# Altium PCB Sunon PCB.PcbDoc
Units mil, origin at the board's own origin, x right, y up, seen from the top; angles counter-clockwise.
Board outline 865.99 x 865.99 mil, 2 copper layers (Top Layer, Bottom Layer), stack 64.8 mil thick; 18 components, 17 nets, 70 pads, 87 vias.
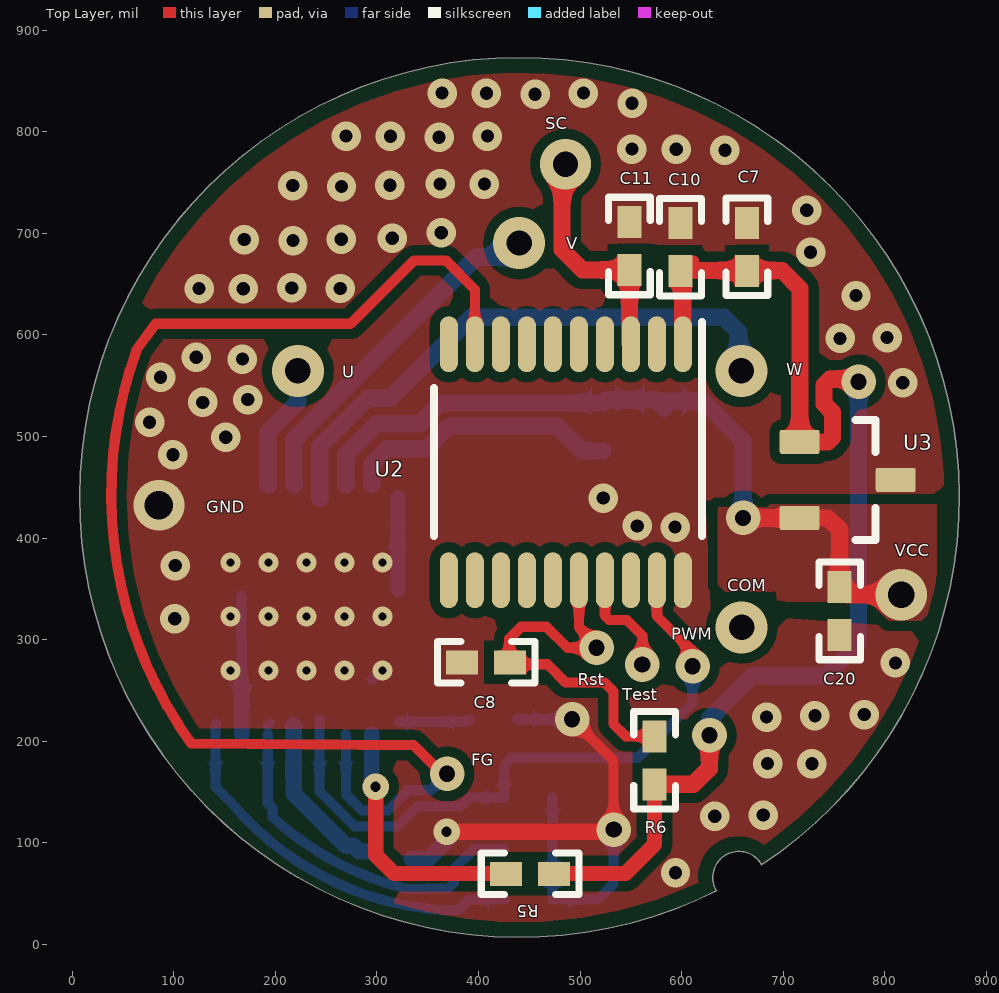
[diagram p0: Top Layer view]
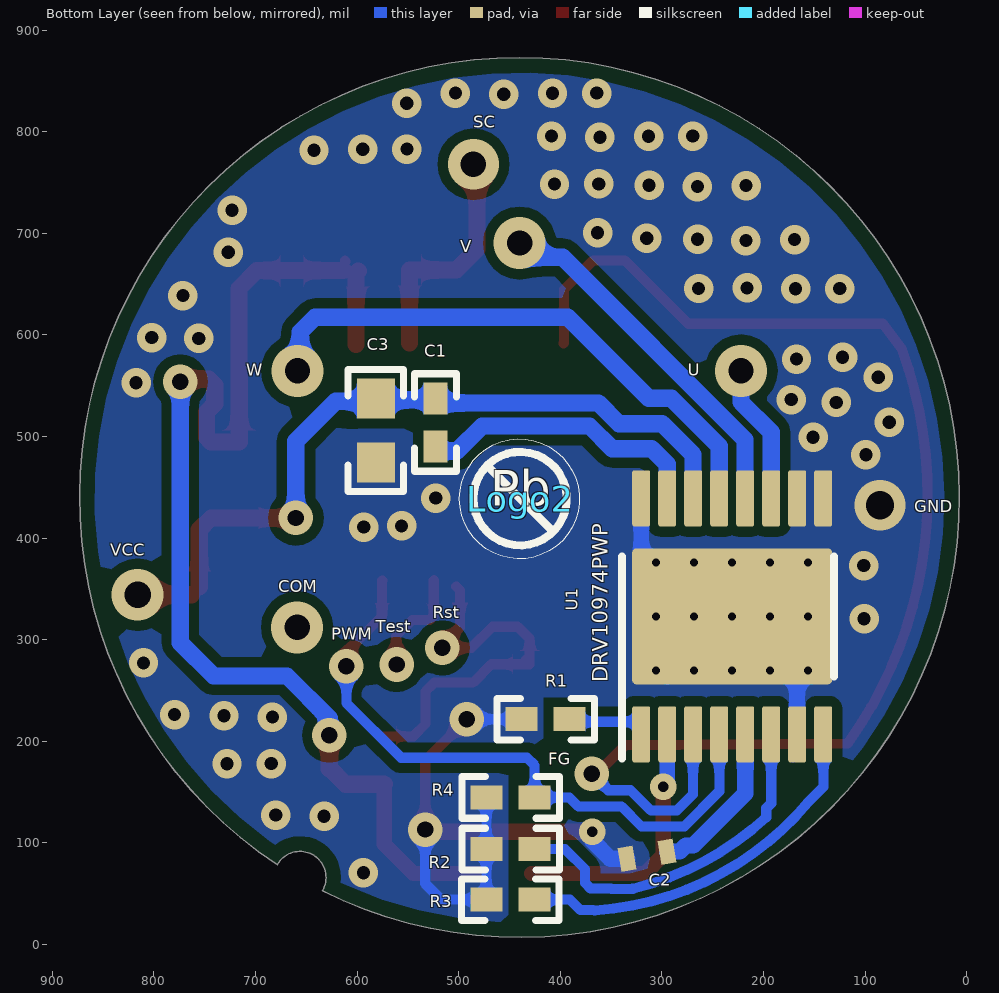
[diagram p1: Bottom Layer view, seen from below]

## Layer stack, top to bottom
Top Solder: solder mask 0.4, Solder Resist, Dk 3.5
Top Layer: signal copper 2.8
Dielectric1: core 59.2, FR-4, Dk 4.8
Bottom Layer: signal copper 2.8
Bottom Solder: solder mask 0.4, Solder Resist, Dk 3.5

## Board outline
634.23,52.84 cw(c440.24,439.95) 678.49,78.39 678.38,78.8 ccw(c656.2,66)

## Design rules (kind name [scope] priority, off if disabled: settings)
AcuteAngle [All] p1: minimum=4.50000000000000E+0001 checktracksonly=FALSE
AssemblyTestPointUsage [All] p1: valid=2
BoardOutlineClearance BoardOutlineClearance_MountingHoles [OnCopper and InComponentClass('Mounting Holes')] p1: gap=15 ignorepadtopadclearanceinfootprint=FALSE
BoardOutlineClearance BoardOutlineClearance_Poly [OnCopper and IsPoly] p2: gap=15 ignorepadtopadclearanceinfootprint=FALSE
BoardOutlineClearance [OnCopper and Not InComponentClass('Logo') and not InComponentClass('FiducialMark') and not InRegion(1000,500,4000,800) and not InPoly] p3: gap=1 ignorepadtopadclearanceinfootprint=FALSE
Clearance Clearance_Keepouts [((IsTrack Or IsArc) And Not InPoly) And IsFree and IsKeepOut vs ((IsTrack Or IsArc) And Not InPoly) And IsFree and IsKeepOut] p1: gap=2 ignorepadtopadclearanceinfootprint=FALSE
Clearance Clearance_Poly [InPolygon] p2: gap=10 ignorepadtopadclearanceinfootprint=FALSE
Clearance Clearance_FiducialMark [IsKeepOut and InComponentClass('FiducialMark') vs IsPad and InComponentClass('FiducialMark')] p3: gap=0 ignorepadtopadclearanceinfootprint=FALSE
Clearance [All] p4: gap=5 ignorepadtopadclearanceinfootprint=FALSE
ComponentClearance ComponentClearance_MountingHoles_FiducialMarks [InComponentClass('Mounting Holes') vs InComponentClass('FiducialMark')] p1: gap=50 collisioncheckmode=3 verticalgap=10 showdistances=FALSE
ComponentClearance ComponentClearance_Shunt [InComponentClass('Header') vs InComponentClass('Shunt')] p2: gap=0 collisioncheckmode=3 verticalgap=0 showdistances=FALSE
ComponentClearance ComponentClearance_Logo [InComponentClass('Logo')] p3: gap=50 collisioncheckmode=3 verticalgap=10 showdistances=FALSE
ComponentClearance ComponentClearance_ScrewToNut [(HasFootprint('NY PMS 440 0025 PH')) vs (HasFootprint('Keystone_1902C'))] p4: gap=5 collisioncheckmode=3 verticalgap=10 showdistances=FALSE
ComponentClearance ComponentClearance_MountingHoles [InComponentClass('Mounting Holes')] p5: gap=250 collisioncheckmode=3 verticalgap=100000 showdistances=FALSE
ComponentClearance ComponentClearance_SmallPassives [HasFootprint('0201*') or HasFootprint('0402*') or HasFootprint('0508') or HasFootprint('0603*') or HasFootprint('0612') or HasFootprint('0805*') or HasFootprint('0815*') or HasFootprint('0830*') or HasFootprint('1206*') or HasFootprint('1210*') or HasFootprint('1808*') or HasFootprint('1812*') or HasFootprint('1825*') or HasFootprint('2010*') or HasFootprint('2220*') or HasFootprint('2225*') or HasFootprint('2512*') or HasFootprint('2728*') or HasFootprint('3518*') vs HasFootprint('0201*') or HasFootprint('0402*') or HasFootprint('0508') or HasFootprint('0603*') or HasFootprint('0612') or HasFootprint('0805*') or HasFootprint('0815*') or HasFootprint('0830*') or HasFootprint('1206*') or HasFootprint('1210*') or HasFootprint('1808*') or HasFootprint('1812*') or HasFootprint('1825*') or HasFootprint('2010*') or HasFootprint('2220*') or HasFootprint('2225*') or HasFootprint('2512*') or HasFootprint('2728*') or HasFootprint('3518*')] p6: gap=14.96 collisioncheckmode=3 verticalgap=10 showdistances=FALSE
ComponentClearance ComponentClearance_THtoSMT [IsThruComponent vs IsSMTComponent] p7: gap=40 collisioncheckmode=3 verticalgap=30 showdistances=FALSE
ComponentClearance ComponentClearance_THtoTH [IsThruComponent vs IsThruComponent] p8: gap=30 collisioncheckmode=3 verticalgap=30 showdistances=FALSE
ComponentClearance [All] p9: gap=5 collisioncheckmode=3 verticalgap=5 showdistances=FALSE
DiffPairsRouting [All] p1: maxlimit=100 minlimit=10 mostfreqgap=10 toplayer_minwidth=15 toplayer_maxwidth=15 toplayer_prefwidth=15 bottomlayer_minwidth=15 bottomlayer_maxwidth=15 bottomlayer_prefwidth=15 maxuncoupledlength=1000
FabricationTestPointUsage TestPointUsage [All] p1: valid=2 allowmultiple=FALSE
FabricationTestpoint Testpoint [All] p1: side=3 testpointundercomponent=TRUE minsize=40 maxsize=100 preferedsize=60 minholesize=0 maxholesize=40 preferedholesize=32 testpointgrid=1 allowsidetop=TRUE allowsidebottom=TRUE usegrid=TRUE gridtolerance=0.01
FanoutControl Fanout_LCC [IsLCC] p1: bgadir=Out bgaviamode=Centered fanoutstyle=Auto fanoutdirection=Alternating viagrid=1 // Fanout_LCC (Default Rule)
FanoutControl Fanout_BGA [IsBGA] p2: bgadir=Out bgaviamode=Centered fanoutstyle=Auto fanoutdirection=Alternating viagrid=1 // Fanout_BGA (Default Rule)
FanoutControl Fanout_Default [All] p4: bgadir=Out bgaviamode=Centered fanoutstyle=Auto fanoutdirection=Alternating viagrid=1 // Fanout_Default (Default Rule)
FanoutControl Fanout_Small [(CompPinCount < 5)] p5: bgadir=Out bgaviamode=Centered fanoutstyle=Auto fanoutdirection=OutThenIn viagrid=1 // Fanout_Small (Default Rule)
HoleSize [All] p1: absolutevalues=TRUE maxlimit=251 minlimit=7.87 maxpercent=80.000 minpercent=20.000
MinimumAnnularRing MinimumAnnularRing_ThermalPadVias [IsVia and InAnyComponent] p1: minimumring=5.91
MinimumAnnularRing [All] p2: minimumring=8
MinimumSolderMaskSliver MinimumSolderMaskSliver_Logo [InComponentClass('Logo') vs InComponentClass('Logo')] p1: minsoldermaskwidth=0.7
MinimumSolderMaskSliver [All] p2: minsoldermaskwidth=3.94
PlaneConnect [InNet('GND')] p1: planeconnectstyle=Direct reliefexpansion=10 reliefentries=4 reliefconductorwidth=10 reliefairgap=10
PolygonConnect B [InNet('GND') vs IsNamedPolygon('TOP_LAYER_GND_P000')] p1: connectstyle=Direct reliefconductorwidth=10 reliefentries=4 polygonreliefangle="90 Angle" airgapwidth=10
PolygonConnect A [InNet('GND') vs IsNamedPolygon('BOTTOM_LAYER_GND_P002')] p2: connectstyle=Direct reliefconductorwidth=10 reliefentries=4 polygonreliefangle="90 Angle" airgapwidth=10
PolygonConnect [All] p3: connectstyle=Direct reliefconductorwidth=10 reliefentries=4 polygonreliefangle="90 Angle" airgapwidth=10
RoutingVias ThermalPadVias [IsVia and InAnyComponent] p1: holewidth=7.87 width=19.68 viastyle="Through Hole" minholewidth=7.87 minwidth=19.68 maxholewidth=12.99 maxwidth=23.62
RoutingVias [All] p2: holewidth=16 width=34 viastyle="Through Hole" minholewidth=7.87 minwidth=26 maxholewidth=40 maxwidth=65
SilkToBoardRegionClearance [Not ((IsComment or IsDesignator) And (Hide <> 'False')) and not InRegion(1000,500,4000,800)] p1:
SilkToSilkClearance SilkToSilkClearance_Pb-FreeLogo [(HasFootprint('Pb-Free_Overlay_Medium') OR HasFootprint('Pb-Free_Overlay_Small')) vs (HasFootprint('Pb-Free_Overlay_Medium') OR HasFootprint('Pb-Free_Overlay_Small'))] p1: silktosilkclearance=0
SilkToSilkClearance [All] p2: silktosilkclearance=4
SilkToSolderMaskClearance SilkToComponentPadClearance [(IsPad or IsFill or IsRegion) and InAnycomponent] p1: minsilkscreentomaskgap=5 clearancetoexposedcopper=TRUE
SilkToSolderMaskClearance "Silk to Solder Mask Opening" [All] p2: minsilkscreentomaskgap=4 clearancetoexposedcopper=FALSE
SolderMaskExpansion [All] p1: expansion=1.97
Width [All] p1: maxlimit=100 minlimit=6 preferedwidth=10 checkconnectedcopper=TRUE
15 further rules are at their usual default settings.

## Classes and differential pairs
component class EVM_Hardware: Logo2
component class "Sunon Layout": C1 C2 C3 C7 C8 C10 C11 C20 R1 R2 R3 R4 R5 R6 U1 U2 U3

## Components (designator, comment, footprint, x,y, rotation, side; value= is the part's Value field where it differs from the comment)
C1 "C1005X5R1H104K050BB" 0402 522.87,513.74 r270 bottom value=0.1uF
C2 "GCM155C71A105KE38D" 0402_070 314.54,87.93 r350 bottom value=1uF
C3 "GRM188R61C106MAALD" 0603 581.66,505.82 r270 bottom value=10uF
C7 "C1005X5R1H104K050BB" 0402 664.16,686.58 r90 top value=0.1uF
C8 "CGA2B2X7R1H222K050BA" 0402 407.46,277.73 r180 top value=2200pF
C10 "C1005X5R1H104K050BB" 0402 598.77,686.37 r90 top value=0.1uF
C11 "CGA2B2X7R1H471K050BA" 0402 548.51,687.4 r90 top value=470pF
C20 "C1005X5R1H104K050BB" 0402 755.39,328.25 r270 top value=0.1uF
Logo2 "Pb-Free Symbol" Pb-Free_Overlay_Small 439.6,438.79 r180 bottom
R1 "CRCW04027K15FKED" 0402 414.45,221.66 r180 bottom value=7.15k
R2 "CRCW04027K15FKED" 0402 448.89,93.82 r180 bottom value=7.15k
R3 "CRCW04027K15FKED" 0402 449.17,44.07 r180 bottom value=7.15k
R4 "CRCW04024K75FKED" 0402 448.89,144.66 r180 bottom value=4.75k
R5 "CRCW040210K0FKED" 0402 450.68,69.49 r180 top value=10.0k
R6 "CRCW040247K0JNED" 0402 573.23,181.2 r270 top value=47k
U1 "DRV10974PWP" PWP0016J_N 230.84,322.93 r90 bottom
U2 "MSP430G2553IPW20" PW0020A_N 485.89,474.64 r270 top
U3 "TLV76033DBZR" DBZ0003A_N 763.32,457.16 r0 top

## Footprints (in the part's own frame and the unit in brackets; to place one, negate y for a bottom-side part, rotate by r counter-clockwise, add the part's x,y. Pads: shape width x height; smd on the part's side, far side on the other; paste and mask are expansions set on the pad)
0402 [mm] "0402 from SM-752 data"
  rect 0.8x0.6 smd: 1(-0.6,0) 2(0.6,0)
  silkscreen extent -1.22,-0.52 1.22,0.52, body extent -0.55,-0.3 0.55,0.3, height 0.6
0402_070 [mil] "SMD, 2-Leads, Body 1.2x0.7mm, Height 0.7mm"
  rect 15x24 smd: 1(-20,0) 2(20,0)
  body extent -24,-14 24,14, height 28
0603 [mm] "0603 from SM-752 data"
  rect 1x0.95 smd: 1(-0.8,0) 2(0.8,0)
  silkscreen extent -1.52,-0.69 1.52,0.69, body extent -0.87,-0.47 0.87,0.47, height 1
DBZ0003A_N [mm] "SOT23, 3-Leads, Body 2.9x1.3mm, Pitch 0.95mm, Lead Span 2.4mm, IPC Medium Density"
  rrect17% 1x0.6 smd: 1(-1.2,0.95) 2(-1.2,-0.95) 3(1.2,0)
  silkscreen extent 0.2,-1.5 0.7,1.5, body extent -1.26,-1.46 1.26,1.46, height 0.98
Pb-Free_Overlay_Small [mil]
  silkscreen extent -46,-46 46,46
PW0020A_N [mm] "TSOP, 20-Leads, Body 6.5x4.4mm, Pitch 0.65mm, IPC Medium Density"
  oval 1.4x0.45 smd: 1(-2.95,2.925) 2(-2.95,2.275) 3(-2.95,1.625) 4(-2.95,0.975) 5(-2.95,0.325) 6(-2.95,-0.325) 7(-2.95,-0.975) 8(-2.95,-1.625) 9(-2.95,-2.275) 10(-2.95,-2.925) 11(2.95,-2.925) 12(2.95,-2.275) 13(2.95,-1.625) 14(2.95,-0.975) 15(2.95,-0.325) 16(2.95,0.325) 17(2.95,0.975) 18(2.95,1.625) 19(2.95,2.275) 20(2.95,2.925)
  silkscreen extent -3.5,-3.3 1.85,3.4, body extent -3.21,-3.25 3.21,3.25, height 1
PWP0016J_N [mm] "TSOP, 16-Leads, Body 5x4.4mm, Pitch 0.65mm, Exposed Pad, IPC Medium Density"
  rrect22% 1.4x0.45 smd: 1(-2.95,2.275) 2(-2.95,1.625) 3(-2.95,0.975) 4(-2.95,0.325) 5(-2.95,-0.325) 6(-2.95,-0.975) 7(-2.95,-1.625) 8(-2.95,-2.275) 9(2.95,-2.275) 10(2.95,-1.625) 11(2.95,-0.975) 12(2.95,-0.325) 13(2.95,0.325) 14(2.95,0.975) 15(2.95,1.625) 16(2.95,2.275)
  rrect6% 3.4x5 smd paste-1.7 mask-1.7: 17(0,0)
  rrect4% 2.46x3.55 on Bottom Solder: 17(0,0)
  rrect4% 2.46x3.55 on Bottom Paste: 17(0,0)
  silkscreen extent -3.55,-2.55 1.5,2.75, body extent -3.2,-2.5 3.2,2.5, height 1.13

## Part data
C1 C7 C10 C20: "CAP, CERM, 0.1 µF, 50 V,+/- 10%, X5R, 0402", Cap_Case=0402, Manufacturer=TDK, Supplier Part Number 1=445-5942-1-ND, TempCo=X5R, Tolerance_%=10, Value1="0.039064 ohm", Value2=50V, ValueDisplayed=0.1µF
C2: "CAP, CERM, 1 µF, 10 V,+/- 10%, X7S, AEC-Q200 Grade 1, 0402", Cap_Case=0402, Manufacturer=MuRata, Supplier Part Number 1=81-GCM155C71A105KE8D, TempCo=X7S, Tolerance_%=10, Value2=10V, ValueDisplayed=1µF
C3: "CAP, CERM, 10 µF, 16 V,+/- 20%, X5R, 0603", Cap_Case=0603, Manufacturer=MuRata, Supplier Part Number 1=GRM188R61C106MAALD-ND, TempCo=X5R, Tolerance_%=20, Value2=16V, ValueDisplayed=10µF
C8: "CAP, CERM, 2200 pF, 50 V,+/- 10%, X7R, AEC-Q200 Grade 1, 0402", Cap_Case=0402, Manufacturer=TDK, Supplier Part Number 1=445-5606-1-ND, TempCo=X7R, Tolerance_%=10, Value1="1.07794 ohm", Value2=50V, ValueDisplayed=2200pF
C11: "CAP, CERM, 470 pF, 50 V,+/- 10%, X7R, AEC-Q200 Grade 1, 0402", Cap_Case=0402, Manufacturer=TDK, Supplier Part Number 1=445-6888-1-ND, TempCo=X7R, Tolerance_%=10, Value1="4.96489 ohm", Value2=50V, ValueDisplayed=470pF
Logo2: library part CMP-0074839-1
R1 R2 R3: "RES, 7.15 k, 1%, 0.063 W, 0402", Manufacturer=Vishay-Dale, Power_W=0.063, Supplier Part Number 1=541-7.15KLCT-ND, TempCo="100 ppm/C", Tolerance_%=1, Value1=1%, Value2=0.063W, Value_Code=7k15, ValueDisplayed=7.15k
R4: "RES, 4.75 k, 1%, 0.063 W, 0402", Manufacturer=Vishay-Dale, Power_W=0.063, Supplier Part Number 1=541-4.75KLCT-ND, TempCo="100 ppm/C", Tolerance_%=1, Value1=1%, Value2=0.063W, Value_Code=4k75, ValueDisplayed=4.75k
R5: "RES, 10.0 k, 1%, 0.063 W, 0402", Manufacturer=Vishay-Dale, Power_W=0.063, Supplier Part Number 1=541-10.0KLCT-ND, TempCo="100 ppm/C", Tolerance_%=1, Value1=1%, Value2=0.063W, Value_Code=10k0, ValueDisplayed=10.0k
R6: "RES, 47 k, 5%, 0.063 W, 0402", Manufacturer=Vishay-Dale, Power_W=0.063, Supplier Part Number 1=541-47KJCT-ND, TempCo="200 ppm/C", Tolerance_%=5, Value1=5%, Value2=0.063W, Value_Code=47k0, ValueDisplayed=47k
U1: library part CMP-0065208-6, "12-V, Three-Phase, Sensorless BLDC Motor Driver, PWP0016J (TSSOP-16)", Alternate Manufacturer="Texas Instruments"
U2: "16 MHz Mixed Signal Microcontroller with 16 KB Flash, 512 B SRAM and 24 GPIOs, -40 to 85 degC, 20-pin SOP (PW), Green (RoHS & no Sb/Br)", Alternate Manufacturer="Texas Instruments", Alternate PartNumber=Equivalent, Frequency(MHz)=16, Pin/Package="0DIESALE, 0WAFERSALE, 20PDIP, 20TSSOP, 28TSSOP, 32QFN", Temp Sensor=Yes
U3: library part CMP-0074893-1, "100-mA, 30-V, Fixed-Output, Linear-Voltage Regulator, DBZ0003A (SOT-23-3)", Alternate Manufacturer="Texas Instruments", Alternate PartNumber=TLV76033DBZT

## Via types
v1: diameter 29, hole 13, Top Layer to Bottom Layer, 54 vias
v2: diameter 19.68, hole 7.87, Top Layer to Bottom Layer, tented both sides, 12 vias
v3: diameter 34, hole 16, Top Layer to Bottom Layer, 9 vias
v4: diameter 51.18, hole 25, Top Layer to Bottom Layer, 4 vias
v5: diameter 19.68, hole 7.87, Top Layer to Bottom Layer, 3 vias
v6: diameter 26, hole 10, Top Layer to Bottom Layer, 2 vias
v7: diameter 51, hole 26, Top Layer to Bottom Layer, 1 vias
v8: diameter 50, hole 28, Top Layer to Bottom Layer, 1 vias
v9: diameter 50, hole 25, Top Layer to Bottom Layer, 1 vias

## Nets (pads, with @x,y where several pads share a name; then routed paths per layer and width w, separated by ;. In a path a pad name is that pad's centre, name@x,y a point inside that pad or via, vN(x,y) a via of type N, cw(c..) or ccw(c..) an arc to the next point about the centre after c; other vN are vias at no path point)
3.3V: C7.1 C10.1 R5.1 R6.2 U2.1 U3.1 | length 1168.3
  Top Layer w10: 611.36,672.44 611.9,672.98 ; v3(627.31,205.93) 627.31,205.27 v3@628.27,204.31
  Top Layer w15: R5.1@475.56,69.72 544.68,69.72 573.23,98.27 R6.2
  Top Layer w17: R6.2 611.41,157.58 627.08,173.25 627.31,173.02 v3(627.31,205.93) ; C10.1 601.05,660.47 U2.1 ; 613.43,663.59 613.75,663.28 698.68,663.28 716.29,645.66 716.29,626.79 U3.1 743.94,494.57 748.26,498.88 748.26,523.87 740.01,532.11 740.01,550.6 746,556.59 v3@766.29,556.59
  Bottom Layer w17: v3(627.31,205.93) 627.31,222.54 668.99,264.22 741.27,264.22 774.01,296.96 v3(774.01,553.79)
ADV: R1.2 U1.1 | length 69.9
  Bottom Layer w10: U1.1@321.96,219.17 388.34,219.17 R1.2
CS: R3.2 U1.8 | length 389.1
  Bottom Layer w10: U1.8@141.91,217.37 141.1,216.56 141.1,154.94 156.83,139.21 ; 155.99,140.07 ccw(c385.8,332.91) 366.12,33.56 ; 368.05,33.78 380.14,33.78 390.43,44.07 R3.2 R3.2@425.39,44.22
FG: U1.3 U2.9 | length 1294.9
  Top Layer w10: v3@368.96,169.71 v3(368.96,167.95) 364.27,167.95 336.1,196.12 117.15,197.79 cw(c458.52,442.46) 63.85,586.11 82.34,610.84 274.12,610.84 336.56,673.29 367.71,673.29 396.35,644.65 396.35,592.05 U2.9@396.74,591.66
  Bottom Layer w10: U1.3 269.42,206.6 269.42,147.75 285.34,131.83 310.91,131.83 330.85,151.77 352.78,151.77 v3(368.96,167.95) v3@363.08,167.95
FR: R5.2 U1.2 | length 257.7
  Top Layer w15: v6(298.69,155.15) 298.69,87.82 316.79,69.72 R5.2@428.31,69.72
  Bottom Layer w15: v6@294.82,159.02 U1.2
  Bottom Layer w16: v6@294.82,159.02 v6(298.69,155.15)
GND: C2.2 C3.2 C7.2 C8.2 C10.2 C11.2 C20.2 R1.1 R2.1 R3.1 R4.1 U1.7 U1.9 U1.10 U1.16 U1.17@230.84,322.93 U2.20 U3.3 | length 858.5
  Top Layer w10: v3(492.01,221.66) 532.97,180.71 v3(532.97,113.05) 532.01,112.1 v3@531.76,112.34
  Top Layer w16: v6(368.6,110.98) 530.4,110.98 v3@531.76,112.34
  Bottom Layer w10: U1.17@166.41,343.2 U1.17@166.87,258.96 ; U1.17@294.82,260.49 U1.17@306.33,272 ; v6@368.6,102.24 v6(368.6,110.98) ; R1.1 v3(492.01,221.66) ; R4.1 472.79,144.38 R3.1 517.19,44.07 532.97,59.86 v3(532.97,113.05)
  Bottom Layer w15: U1.7 U1.17@166.87,258.96 ; U1.16 320.41,402.45 U1.17@320.83,349.25
  Bottom Layer w16: C2.2 350.81,84.46 v6@368.6,102.24
  other v1: 593.84,70.61 632.53,126.17 680.12,127.35 684.52,177.97 728.08,177.75 683.42,223.83 731.02,225 779.63,226.19 810.25,277.09 101.03,320.54 101.41,372.85 593.43,410.74 556.19,411.98 522.67,439.29 99.21,482.06 151.2,499.16 76.21,513.92 128.46,533.46 172.74,536.25 817.59,552.81 86.98,558.19 167.55,576.14 122.13,577.91 755.87,596.48 802.14,597.28 771.49,638.58 124.92,645.58 168.47,645.36 216.13,646.14 263.97,645.6 726.8,681.2 217.35,692.81 169.45,693.75 264.95,693.99 314.95,695.01 363.36,700.39 723.08,722.58 265.1,745.95 217.2,746.88 312.7,747.13 362.19,748.58 405.74,748.35 642.43,781.7 550.97,782.86 594.53,782.63 361.09,794.43 269.63,795.59 313.19,795.36 408.68,795.61 551.11,828.01 455.6,836.79 364.15,837.95 407.7,837.73 503.2,837.97
  other v2: 156.04,269.78 193.44,269.78 230.84,269.78 268.25,269.78 305.65,269.78 156.04,322.93 305.65,322.93 156.04,376.08 193.44,376.08 230.84,376.08 268.25,376.08 305.65,376.08
  other v5: 193.44,322.93 230.84,322.93 268.25,322.93
  other v8: 85.35,432.27
PWM: R4.2 U1.4 U2.19 | length 656.4
  Top Layer w10: U2.19@575.28,357.91 575.57,357.63 575.57,322.87 610.59,287.84 v3(610.59,273.73)
  Bottom Layer w10: U1.4@243.94,221.79 243.56,221.41 243.54,206.79 243.48,162.62 243.48,150.71 278.04,116.15 320.15,116.15 339.69,135.69 382.21,135.69 391.18,144.66 R4.2 425.27,176.28 432.75,183.76 556.67,183.76 610.59,237.68 v3(610.59,273.73)
Reset: C8.1 R6.1 U2.16 | length 388.6
  Top Layer w10: C8.1@430.18,275.7 C8.1@433.12,275.7 ; C8.1@430.18,278.47 430.18,300.9 441.98,312.7 466.77,312.7 487.55,291.93 v3(516.12,291.93) 516.12,294.92 498.88,312.17 498.88,348.77 U2.16@502.39,352.29 ; C8.1@433.67,280.32 C8.1 C8.1@433.12,275.7 ; R6.1 544.82,204.82 532.66,216.98 532.66,249.11 524.08,257.69 485.85,257.69 467.85,275.7 C8.1@433.12,275.7
RMP: R2.2 U1.6 | length 358.9
  Bottom Layer w10: U1.6@192.18,214.98 U1.6@194.57,217.37 ; U1.6 192.46,138.94 197.27,134.12 197.27,125.24 ccw(c400.29,346.11) 328.66,54.79 ; 328.79,54.65 349.77,54.65 350.02,54.91 370,54.91 375.69,60.6 375.69,74.18 395.33,93.82 R2.2 R2.2@424.81,94.28
"Speed Control": C11.1 U2.3 | length 255.3
  Top Layer w10: v9@475.89,766.96 v9@482.1,760.75 ; v9@476.13,761.95 482.13,767.95 v9(485.52,767.95) ; U2.3@548.51,592.13 U2.3
  Top Layer w17: v9@482.1,760.75 482.1,683.94 502.26,663.78 C11.1 U2.3@548.51,592.13
  Bottom Layer w10: v9@477.08,765.29 479.75,767.95 v9(485.52,767.95)
Test: U2.17 | length 117.8
  Top Layer w10: U2.17 524.51,358.26 524.51,323.54 528.65,319.4 545.87,319.4 561.24,304.03 ; v3(561.12,275.52) 569.14,275.52 v3@570.42,276.8 ; 561.43,303.34 561.59,275.53 v3@561.59,275.2
U: U1.11 | length 128.3
  Bottom Layer w10: v4@219.91,564.58 v4(222.14,564.58)
  Bottom Layer w15: U1.11@192.43,453.04 U1.11@194.01,451.46
  Bottom Layer w17: U1.11@192.43,453.04 192.43,504.08 222.14,533.78 v4(222.14,564.58)
V: U1.12 | length 348
  Bottom Layer w10: v4@426.01,676.31 v4(440.04,690.34)
  Bottom Layer w15: U1.12@218.18,452.88 U1.12@219.6,451.46
  Bottom Layer w17: U1.12@218.18,452.88 218.18,496.83 397.66,676.31 v4@426.01,676.31
V1P8: C2.1 U1.5 | length 167.6
  Bottom Layer w16: U1.5@217.98,214.69 217.98,148.55 269.08,97.44 276.42,97.44 282.46,91.4 C2.1
  Bottom Layer w17: U1.5@217.65,215.12 U1.5@218.31,214.46
VCC: C1.1 C3.1 C20.1 U1.14 U3.2 | length 779.4
  Top Layer w10: C20.1@754.54,352.69 C20.1@763.02,344.21 ; v7(816.05,344.21) 816.05,332.28 v7@820.72,327.62
  Top Layer w17: v3(660.32,419.76) U3.2 743.8,419.76 755.39,408.17 C20.1 ; C20.1@763.02,344.21 v7(816.05,344.21)
  Bottom Layer w10: C1.1@522.31,532.99 C1.1@525.39,536.06
  Bottom Layer w17: U1.14@269.31,452.48 269.31,482.04 299.83,512.56 342.19,512.56 362.62,532.99 C1.1@522.31,532.99 ; C1.1@525.39,536.06 574.51,536.06 C3.1@582.78,527.8 ; C3.1@581.38,534.65 621.04,534.65 660.32,495.37 v3(660.32,419.76)
VCP: C1.2 U1.15 | length 272.8
  Bottom Layer w17: U1.15@294.81,453.02 294.81,472.49 310.17,487.85 348.87,487.85 371.3,510.28 476.86,510.28 501.39,485.75 C1.2@522.31,485.75
W: U1.13 | length 561.6
  Bottom Layer w15: v4@656,567.12 v4(658.66,564.46)
  Bottom Layer w17: U1.13 243.64,490.43 290.68,537.48 313,537.48 392.74,617.22 641.5,617.22 656,602.72 v4@656,567.12
pads on no net: U1.17@230.84,322.93 U2.2 U2.4 U2.5 U2.6 U2.7 U2.8 U2.10 U2.11 U2.12 U2.13 U2.14 U2.15 U2.18
copper on no net: | length 69737.8
  Bottom Layer w1: 4689.2,-274.34 4788.88,-174.66 4908.88,-54.66 5028.88,65.34 5148.88,185.34 5268.88,305.34 5388.88,425.34 5508.88,545.34 ; 4689.2,-214.34 4728.88,-174.66 4848.88,-54.66 4968.88,65.34 5088.88,185.34 5208.88,305.34 5328.88,425.34 5448.88,545.34 ; 4689.2,-154.34 4788.88,-54.66 4908.88,65.34 5028.88,185.34 5148.88,305.34 5268.88,425.34 5388.88,545.34 ; 4689.2,-94.34 4728.88,-54.66 4848.88,65.34 4968.88,185.34 5088.88,305.34 5208.88,425.34 5328.88,545.34 ; 4689.2,-34.34 4788.88,65.34 4908.88,185.34 5028.88,305.34 5148.88,425.34 5268.88,545.34 ; 4689.2,25.66 4728.88,65.34 4848.88,185.34 4968.88,305.34 5088.88,425.34 5208.88,545.34 ; 4689.2,85.66 4788.88,185.34 4908.88,305.34 5028.88,425.34 5148.88,545.34 ; 4689.2,145.66 4728.88,185.34 4848.88,305.34 4968.88,425.34 5088.88,545.34 ; 4689.2,205.66 4788.88,305.34 4908.88,425.34 5028.88,545.34 ; 4689.2,265.66 4728.88,305.34 4848.88,425.34 4968.88,545.34 ; 4689.2,325.66 4788.88,425.34 4908.88,545.34 ; 4689.2,385.66 4728.88,425.34 4848.88,545.34 ; 4689.2,445.66 4788.88,545.34 ; 4689.2,505.66 4728.88,545.34 ; 4728.88,-294.66 4848.88,-174.66 4968.88,-54.66 5088.88,65.34 5208.88,185.34 5328.88,305.34 5448.88,425.34 5568.88,545.34 ; 4788.88,-294.66 4908.88,-174.66 5028.88,-54.66 5148.88,65.34 5268.88,185.34 5388.88,305.34 5508.88,425.34 5628.88,545.34 ; 4848.88,-294.66 4968.88,-174.66 5088.88,-54.66 5208.88,65.34 5328.88,185.34 5448.88,305.34 5568.88,425.34 5688.88,545.34 ; 4908.88,-294.66 5028.88,-174.66 5148.88,-54.66 5268.88,65.34 5388.88,185.34 5508.88,305.34 5628.88,425.34 5748.88,545.34 ; 4968.88,-294.66 5088.88,-174.66 5208.88,-54.66 5328.88,65.34 5448.88,185.34 5568.88,305.34 5688.88,425.34 5808.88,545.34 ; 5028.88,-294.66 5148.88,-174.66 5268.88,-54.66 5388.88,65.34 5508.88,185.34 5628.88,305.34 5748.88,425.34 5808.88,485.34 ; 5088.88,-294.66 5208.88,-174.66 5328.88,-54.66 5448.88,65.34 5568.88,185.34 5688.88,305.34 5808.88,425.34 ; 5148.88,-294.66 5268.88,-174.66 5388.88,-54.66 5508.88,65.34 5628.88,185.34 5748.88,305.34 5808.88,365.34 ; 5208.88,-294.66 5328.88,-174.66 5448.88,-54.66 5568.88,65.34 5688.88,185.34 5808.88,305.34 ; 5268.88,-294.66 5388.88,-174.66 5508.88,-54.66 5628.88,65.34 5748.88,185.34 5808.88,245.34 ; 5328.88,-294.66 5448.88,-174.66 5568.88,-54.66 5688.88,65.34 5808.88,185.34 ; 5388.88,-294.66 5508.88,-174.66 5628.88,-54.66 5748.88,65.34 5808.88,125.34 ; 5448.88,-294.66 5568.88,-174.66 5688.88,-54.66 5808.88,65.34 ; 5508.88,-294.66 5628.88,-174.66 5748.88,-54.66 5808.88,5.34 ; 5568.88,-294.66 5688.88,-174.66 5808.88,-54.66 ; 5628.88,-294.66 5748.88,-174.66 5808.88,-114.66 ; 5688.88,-294.66 5808.88,-174.66 ; 5748.88,-294.66 5808.88,-234.66
  Bottom Layer w15: 1270.08,-174.66 1679.99,-174.66 2609.74,-174.66 3469.5,-174.66 4119.34,-174.66 4689.2,-174.66 5808.88,-174.66 ; 1270.08,-54.66 1679.99,-54.66 2609.74,-54.66 3469.5,-54.66 4119.34,-54.66 4689.2,-54.66 5808.88,-54.66 ; 1270.08,65.34 1679.99,65.34 2609.74,65.34 3469.5,65.34 4119.34,65.34 4689.2,65.34 5808.88,65.34 ; 1270.08,185.34 1679.99,185.34 2609.74,185.34 3469.5,185.34 4119.34,185.34 4689.2,185.34 5808.88,185.34 ; 1270.08,305.34 1679.99,305.34 2609.74,305.34 3469.5,305.34 4119.34,305.34 4689.2,305.34 5808.88,305.34 ; 1270.08,425.34 1679.99,425.34 2609.74,425.34 3469.5,425.34 4119.34,425.34 4689.2,425.34 5808.88,425.34 ; 1270.08,545.34 5808.88,545.34 ; 1679.99,665.34 1679.99,-294.66 ; 2609.74,665.34 2609.74,-294.66 ; 3469.5,665.34 3469.5,-294.66 ; 4119.34,665.34 4119.34,-294.66 ; 4689.2,665.34 4689.2,-294.66 ; 1679.99,-294.66 2609.74,-294.66 ; 1679.99,-294.66 1270.08,-294.66 1270.08,665.34 5808.88,665.34 5808.88,-294.66 4689.2,-294.66 ; 2609.74,-294.66 3469.5,-294.66 ; 3469.5,-294.66 4119.34,-294.66 ; 4119.34,-294.66 4689.2,-294.66
  other v4: 659.03,312.13

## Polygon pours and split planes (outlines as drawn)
GND on Top Layer "TOP_LAYER_GND_P006" (solid, remove dead copper, pour order 6): 1.44,2.62 2.44,1.62 885.24,1.62 885.24,302.38 876.75,310.87 874.75,308.87 628.39,326.31 622.98,437.27 886.74,437.27 886.74,879.92 883.74,882.92 881.74,880.92 1.44,880.92 1.44,5.12 2.44,4.12
VCC on Top Layer "TOP_LAYER_VCC_P004" (solid, remove dead copper, pour order 4): 691.66,334.56 694.25,337.15 790.88,337.15 790.88,330.92 803.34,318.45 836.07,318.45 851.14,333.52 851.14,433.26 686.98,433.26 683.87,430.14 635.55,430.14 635.55,349.1 640.23,344.43 642.83,347.02 692.7,347.02 692.7,339.23 693.22,338.71
GND on Bottom Layer "BOTTOM_LAYER_GND_P002" (solid, remove dead copper, pour order 2): -2,1.24 -1.39,0.63 883.56,0.63 883.56,865.3 870.66,878.2 1.07,878.2 1.07,3.09

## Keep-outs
Keep-Out Layer:
  text ".Layer_Name" at 438.6,-797.71 h60

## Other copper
Top Layer:
  text ".Layer_Name" at 438.6,-797.71 h60
Bottom Layer:
  pour cut-out: 180.4,148.64 179.49,149.55 179.49,178.3 152.8,178.3 152.57,178.07 153.02,177.62 153.02,155.94 155.08,155.94 162.15,148.87 162.61,149.32 180.18,149.32
  text "Layer" at 1330.08,575.34 h60
  text "Name" at 1739.99,575.34 h60
  text "Material" at 2669.74,575.34 h60
  text "Thickness" at 3529.5,575.34 h60
  text "Constant" at 4179.34,575.34 h60
  text "Board Layer Stack" at 4749.2,575.34 h60
  text "1" at 1330.08,455.34 h60
  text "Top Overlay" at 1739.99,455.34 h60
  text "2" at 1330.08,335.34 h60
  text "Top Solder" at 1739.99,335.34 h60
  text "Solder Resist" at 2669.74,335.34 h60
  text "0.40mil" at 3529.5,335.34 h60
  text "3.5" at 4179.34,335.34 h60
  text "3" at 1330.08,215.34 h60
  text "Top Layer" at 1739.99,215.34 h60
  text "Copper" at 2669.74,215.34 h60
  text "2.80mil" at 3529.5,215.34 h60
  text "4" at 1330.08,95.34 h60
  text "Dielectric1" at 1739.99,95.34 h60
  text "FR-4" at 2669.74,95.34 h60
  text "59.20mil" at 3529.5,95.34 h60
  text "4.8" at 4179.34,95.34 h60
  text "5" at 1330.08,-24.66 h60
  text "Bottom Layer" at 1739.99,-24.66 h60
  text "Copper" at 2669.74,-24.66 h60
  text "2.80mil" at 3529.5,-24.66 h60
  text "6" at 1330.08,-144.66 h60
  text "Bottom Solder" at 1739.99,-144.66 h60
  text "Solder Resist" at 2669.74,-144.66 h60
  text "0.40mil" at 3529.5,-144.66 h60
  text "3.5" at 4179.34,-144.66 h60
  text "7" at 1330.08,-264.66 h60
  text "Bottom Overlay" at 1739.99,-264.66 h60
  text ".Layer_Name" at 438.6,-797.71 h60

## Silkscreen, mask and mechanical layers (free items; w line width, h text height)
Top Overlay:
  text "SC" at 465.84,802.23 h12
  text "V" at 486.12,684 h12
  text "W" at 702.65,560.03 h12
  text "U" at 265.8,557.87 h12
  text "GND" at 132.09,424.7 h12
  text "VCC" at 809.48,382.16 h12
  text "COM" at 644.81,347.86 h12
  text "PWM" at 589.78,299.97 h12
  text "Rst" at 497.56,254.95 h12
  text "Test" at 541.37,240.3 h12
  text "FG" at 392.95,176.1 h12
  text ".Layer_Name" at 438.6,-797.71 h60
Bottom Overlay:
  circle w1: c440.24,438.58 r59.06
  text "SC" at 485.76,803.66 h12
  text "V" at 498.58,681.3 h12
  text "U" at 274.46,559.5 h12
  text "W" at 709.15,559.5 h12
  text "GND" at 51.78,425.51 h12
  text "VCC" at 843,382.76 h12
  text "COM" at 677.55,346.79 h12
  text "Rst" at 525.61,320.81 h12
  text "Test" at 581.61,307.34 h12
  text "PWM" at 625.6,299.97 h12
  text "FG" at 411.89,176.96 h12
  text ".Layer_Name" at 438.6,-797.71 h60
Top Paste:
  text ".Layer_Name" at 438.6,-797.71 h60
Bottom Paste:
  text ".Layer_Name" at 438.6,-797.71 h60
Top Solder:
  text ".Layer_Name" at 438.6,-797.71 h60
  text ".Layer_Name" at 438.6,-797.71 h60
Bottom Solder:
  text ".Layer_Name" at 438.6,-797.71 h60
Drill Guide:
  text ".Layer_Name" at 438.6,-797.71 h60
M1 Board Outline:
  lines w10: 634.03,53.2 cw(c656.2,66) 678.38,78.8 ; 634.23,52.84 cw(c440.24,439.95) 678.5,78.39
  text ".Layer_Name" at 438.6,-797.71 h60
M2 Board Dimensions:
  rectangle: -138.4,-214.21 -13.4,-89.21
  rectangle: -13.4,-339.21 361.6,-214.21
  lines w7: -138.4,-214.21 861.6,-214.21 ; -13.4,-339.21 -13.4,-89.21 ; 111.6,-339.21 111.6,-89.21 ; 361.6,-339.21 361.6,-89.21 ; 611.6,-339.21 611.6,-89.21 ; -138.4,-339.21 861.6,-339.21 861.6,-89.21 -138.4,-89.21 -138.4,-339.21
  text ".Layer_Name" at 438.6,-797.71 h60
M3 3D STEP Top:
  text ".Layer_Name" at 438.6,-797.71 h60
M4 3D STEP Bottom:
  text ".Layer_Name" at 438.6,-797.71 h60
M5 Assembly Top:
  lines w10: -430.4,-869.38 6169.6,-869.38 ; -430.4,-666.05 6171.6,-666.05 ; -430.4,-462.71 -430.4,-1072.71 3574.6,-1072.71 6171.6,-1072.71 6171.6,-462.71 -429.9,-462.71 -429.9,-1072.71 1145.6,-1072.71 ; 2034.6,-1072.71 2034.6,-462.71 ; 3301.6,-666.05 3301.6,-462.71 ; 4141.6,-666.05 4141.6,-462.71 ; 4763.6,-1079.21 4763.6,-876.38
  text "COMPONENTS MARKED 'DNP' SHOULD NOT BE POPULATED." at 1015.1,-257.71 h60
  text "ASSEMBLY VARIANT:" at 1014.6,-373.21 h60
  text ".VariantName" at 2050.6,-373.21 h60
  text "PCB VIEWED FROM TOP SIDE" at -366.9,-594.88 h60
  text "BOARD #:" at 2109.6,-594.88 h60
  text ".PRJ_Number" at 2655.1,-594.88 h60
  text "REV:" at 3499.6,-594.88 h60
  text ".PCB_Rev" at 3791.1,-594.88 h60
  text "SVN REV:" at 4337.6,-594.88 h60
  text ".VersionControl_RevNumber" at 4843.6,-594.88 h60
  text "TID #:" at 2109.6,-798.21 h60
  text ".TID" at 2655.1,-798.21 h60
  text "PLOT NAME =" at -366.9,-1003.55 h60
  text ".plot_File_Name" at 438.6,-1003.55 h60
  text "GENERATED    :" at 2111.6,-1003.55 h60
  text ".Print_Date" at 2981.1,-1003.55 h60
  text ".Print_Time" at 3710.1,-1003.55 h60
  text "TEXAS INSTRUMENTS" at 4974.6,-1003.55 h60
M6 Assembly Bottom:
  lines w10: -430.9,-666.55 6171.1,-666.55 ; -428.9,-869.88 6171.1,-869.88 ; 977.1,-1079.71 977.1,-876.88 ; 1599.1,-666.55 1599.1,-463.21 ; 2439.1,-666.55 2439.1,-463.21 ; 3706.1,-1073.21 3706.1,-463.21 ; 4595.1,-1073.21 6170.6,-1073.21 6170.6,-463.21 -430.9,-463.21 -430.9,-1073.21 2166.1,-1073.21 6171.1,-1073.21 6171.1,-463.21
  text "COMPONENTS MARKED 'DNP' SHOULD NOT BE POPULATED." at 5963.6,-257.21 h60
  text ".VariantName" at 4919.6,-373.21 h60
  text "ASSEMBLY VARIANT:" at 5958.6,-373.21 h60
  text ".VersionControl_RevNumber" at 897.1,-595.38 h60
  text "SVN REV:" at 1403.1,-595.38 h60
  text ".PCB_Rev" at 1949.6,-595.38 h60
  text "REV:" at 2241.1,-595.38 h60
  text ".PRJ_Number" at 3085.6,-595.38 h60
  text "BOARD #:" at 3631.1,-595.38 h60
  text "PCB VIEWED FROM BOTTOM SIDE" at 6107.6,-595.38 h60
  text ".TID" at 3085.6,-798.71 h60
  text "TID #:" at 3631.1,-798.71 h60
  text "TEXAS INSTRUMENTS" at 766.1,-1004.05 h60
  text ".Print_Time" at 2030.6,-1004.05 h60
  text ".Print_Date" at 2759.6,-1004.05 h60
  text "GENERATED    :" at 3629.1,-1004.05 h60
  text ".plot_File_Name" at 5302.1,-1004.05 h60
  text "PLOT NAME =" at 6107.6,-1004.05 h60
M9 Title Sheet:
  drawing of 57 lines, arcs and shapes, not listed
  text "1" at 601.44,8097.29 h70
  text "2" at 3097.1,8097.29 h70
  text "3" at 5586.44,8097.29 h70
  text "4" at 8093.11,8097.29 h70
  text "5" at 10592.1,8097.29 h70
  text "6" at 13097.1,8097.29 h70
  text "A" at -554.9,6954.29 h70
  text "A" at 14245.1,6954.29 h70
  text "B" at -554.9,4574.29 h70
  text "B" at 14245.1,4574.29 h70
  text "C" at -554.9,2199.29 h70
  text "C" at 14245.1,2199.29 h70
  text "PROJECT TITLE:" at 11205.1,338.29 h45
  text ".PRJ_Title" at 11255.1,204.96 h70
  text "DESIGNED FOR:" at 11205.1,37.29 h45
  text ".PRJ_Customer" at 11255.1,-102.71 h70
  text "D" at -554.9,-170.71 h70
  text "D" at 14245.1,-170.71 h70
  text "FILE NAME:" at 11205.1,-262.71 h45
  text ".PCB_File_Name_No_Path" at 11255.1,-382.71 h70
  text "Texas Instruments (TI) and/or its licensors do not warrant the accuracy or completeness of this specification" at 6235.6,-544.55 h45
  text "ENGINEER:" at 11205.1,-552.71 h45
  text "LAYOUT BY:" at 12710.1,-552.71 h45
  text "or any information contained therein. TI and/or its licensors do not warrant that this design will meet" at 6190.61,-657.22 h45
  text ".PRJ_Engineer" at 11255.1,-707.7 h70
  text ".PCB_Layout" at 12760.6,-707.7 h70
  text "the specifications, will be suitable for your application or fit for any particular purpose, or will operate in" at 6190.61,-769.88 h45
  text ".Layer_Name" at 438.6,-797.71 h60
  text "ALTIUM DESIGNER VERSION:" at 12710.1,-862.71 h45
  text "an implementation. TI and/or its licensors do not warrant that the design is production worthy. You should" at 6190.61,-882.55 h45
  text "completely validate and test your design implementation to confirm the system functionality for your application." at 6235.6,-995.21 h45
  text ".print_Scale" at 11255.1,-996.04 h70
  text ".Application_BuildNumber" at 12760.6,-996.04 h70
  text "1" at 601.44,-1202.71 h70
  text "2" at 3097.1,-1202.71 h70
  text "3" at 5586.44,-1202.71 h70
  text "4" at 8093.11,-1202.71 h70
  text "5" at 10592.1,-1202.71 h70
  text "6" at 13097.1,-1202.71 h70
M10 Fab Notes:
  drawing of 189 lines, arcs and shapes, not listed
  text "DESIGN INFORMATION" at 12243.62,6416.96 h60
  text "MIN. TRACK WIDTH:" at 11599.06,6284.84 h60
  text "8" at 12695.3,6284.84 h60
  text "MIL" at 12850.06,6284.84 h60
  text "MIN. CLEARANCE:" at 11599.06,6160.71 h60
  text "0.2" at 12635.3,6160.71 h60
  text "mm" at 12850.06,6160.71 h60
  text "MIN. VIA PAD SIZE:" at 11599.06,6036.58 h60
  text "24" at 12665.31,6036.59 h60
  text "MIL" at 12850.06,6036.58 h60
  text "0.05mm (2MIL)" at 12294.06,5906.68 h60
  text "MINIMUM ANNULAR RING" at 11269.83,5898.46 h60
  text "EXTERNAL" at 13002.06,5898.46 h60
  text "PER" at 11469.83,5788.34 h60
  text "IPC-D-275 CLASS 2 LEVEL C" at 11689.83,5788.33 h60
  text "MIL, HOLES" at 13178.06,5687.86 h60
  text "+/-" at 12785.6,5679.27 h60
  text "+/-" at 13639.6,5679.27 h60
  text "REGISTRATION TOLERANCES:" at 11269.83,5678.21 h60
  text "METAL" at 12469.6,5678.21 h60
  text "5" at 13045.8,5678.21 h60
  text "3" at 13878.8,5678.21 h60
  text "MIL" at 13995.06,5678.21 h60
  text "HOLE SIZE TOLERANCE (UNLESS OTHERWISE SPECIFIED):" at 11269.83,5579.89 h60
  text "+/-" at 13639.6,5577.02 h60
  text "3" at 13878.8,5575.96 h60
  text "MIL" at 13995.06,5575.95 h60
  text "MATERIAL:" at 11195.06,5438.31 h60
  text "FR-4 High Tg" at 12181.5,5309.78 h60
  text "X" at 12037.06,5301.79 h60
  text "FR-408" at 11616.06,5297.28 h60
  text "OTHER" at 13104.06,5297.28 h60
  text "62 MIL (1.6mm) +/-10%" at 11936.16,5154.25 h60
  text "X" at 11816.06,5151.79 h60
  text "THICKNESS:" at 11269.83,5146.03 h60
  text "OTHER" at 13221.06,5146.03 h60
  text "TOLERANCE:" at 11269.83,5007.71 h60
  text "X" at 12118.06,5007.71 h60
  text "ANSI IPC-6012 TYPE 3 CLASS 2" at 12296.08,5007.71 h60
  text "OTHER +/-" at 12296.06,4863.52 h60
  text "BOW & TWIST:" at 11269.83,4718.33 h60
  text "X" at 12118.06,4718.33 h60
  text "ANSI IPC-6012 TYPE 3 CLASS 2" at 12296.08,4718.33 h60
  text "OTHER +/-" at 12296.06,4571.64 h60
  text "DRILLING:" at 11195.06,4441.02 h60
  text "NC_DRILL FILES" at 12956.06,4335.83 h60
  text "REFERENCE:" at 11269.83,4331.89 h60
  text "X" at 11927.06,4331.79 h60
  text "AS SHOWN" at 12105.06,4331.89 h60
  text "X" at 12828.06,4331.89 h60
  text "OTHER" at 13254.06,4189.64 h60
  text "PTH COPPER THICKNESS:" at 11269.51,4186.11 h60
  text "X" at 12408.74,4186.11 h60
  text "20-30 um" at 12536.74,4186.11 h60
  text "BOARD FINISH:" at 11195.06,4038.51 h60
  text "SILKSCREEN:" at 11350.28,3928.39 h60
  text "X" at 12308.06,3928.39 h60
  text "TOP" at 12425.06,3928.39 h60
  text "X" at 12818.06,3928.39 h60
  text "BOTTOM" at 12936.06,3928.39 h60
  text "SILKSCREEN COLOR:" at 11350.28,3773.2 h60
  text "X" at 12307.06,3773.2 h60
  text "WHITE" at 12425.06,3773.2 h60
  text "OTHER" at 12936.06,3773.2 h60
  text "X" at 12438.06,3629.75 h60
  text "GREEN" at 12556.06,3629.75 h60
  text "OTHER" at 13174.06,3629.75 h60
  text "SOLDER RESIST COLOR:" at 11350.28,3622.88 h60
  text "X" at 12438.06,3475.5 h60
  text "MATTE" at 12556.06,3475.5 h60
  text "SEMI-GLOSS" at 13173.6,3474.86 h60
  text "IMMERSION GOLD (ENIG)" at 12256.06,3302.73 h60
  text "ENEPIG" at 13593.6,3295.51 h60
  text "SURFACE FINISH:" at 11195.06,3294.51 h60
  text "X" at 12078.06,3294.51 h60
  text "IMM. TIN/SILVER OR EQUIV" at 11524.6,3157.19 h60
  text "OTHER" at 12956.06,3153.25 h60
  text "ARRAY/PANEL:" at 11195.06,2997.88 h60
  text "CUT AND TRIM PER M1 BOARD OUTLINE" at 12256.06,2989.65 h60
  text "N.C. ROUTE" at 12256.06,2853.69 h60
  text "X" at 12944.06,2853.69 h60
  text "V. SCORE" at 13122.06,2853.69 h60
  text "CERTIFICATION:" at 11195.06,2724.56 h60
  text "MATERIALS AND WORKMANSHIP FOR ALL PCBS" at 11920.06,2724.56 h60
  text "TO MEET OR EXCEED THE REQUIREMENTS OF:" at 11920.06,2630.5 h60
  text "X" at 11557.57,2501.87 h60
  text "ANSI IPC-A-600F CLASS ->" at 11685.56,2501.87 h60
  text "X" at 13333.57,2501.87 h60
  text "2" at 13443.56,2501.87 h60
  text "1" at 13128.56,2500.37 h60
  text "3" at 13797.56,2500.37 h60
  text "X" at 12369.57,2354.18 h60
  text "RoHS" at 12497.56,2354.18 h60
  text "OTHER" at 13141.96,2354.18 h60
  text "PER ORDER" at 13539.02,2354.18 h60
  text "ALL BOARDS MUST MEET OR EXCEED UL94-V0 REQUIREMENTS." at 11222.6,2200.36 h60
  text "PCB MUST BEAR THE UL94V-0 UL REGISTERED MATERIAL ID NUMBER" at 11222.6,2084.29 h60
  text "ADDITIONAL REQUIREMENTS:" at 11195.06,1914.87 h60
  text "MICROSECTION:" at 11269.83,1807.74 h60
  text "YES" at 12175.56,1807.74 h60
  text "REQUIRED" at 13037.06,1663.41 h60
  text "BARE BOARD ELEC. TEST:" at 11269.83,1660.55 h60
  text "NONE" at 12575.56,1660.55 h60
  text "X" at 12919.06,1660.55 h60
  text "PER ORDER" at 13629.06,1660.55 h60
  text "XX MIL VIAS REQUIRE NON-CONDUCTIVE FILL AND PLANARIZE" at 11437.98,1455.61 h59
  text "XX MIL VIAS REQUIRE CONDUCTIVE FILL AND PLANARIZE" at 11445.98,1351.63 h60
  text "OUTER XX MIL TRACES REQUIRE 50 OHM SINGLE-ENDED IMPEDANCE" at 11444.99,1188.25 h58
  text "LAYER 2 & 3 (INNER LAYERS) XX MIL WIDE, XX MIL SPACE / TRACES REQUIRE 100 OHM DIFFERENTIAL IMPEDANCE" at 11436.99,952.53 h60
  text ".Layer_Name" at 438.6,-797.71 h60
M11 Gerber Information:
  lines w10: -430.4,-869.38 6169.6,-869.38 ; -430.4,-666.05 6171.6,-666.05 ; -430.4,-462.71 -430.4,-1072.71 3574.6,-1072.71 6171.6,-1072.71 6171.6,-462.71 -429.9,-462.71 -429.9,-1072.71 1145.6,-1072.71 ; 2034.6,-1072.71 2034.6,-462.71 ; 3301.6,-666.05 3301.6,-462.71 ; 4141.6,-666.05 4141.6,-462.71 ; 4763.6,-1079.21 4763.6,-876.38
  text "ALL ARTWORK VIEWED FROM TOP SIDE" at -366.9,-594.88 h60
  text "BOARD #:" at 2109.6,-594.88 h60
  text ".PRJ_Number" at 2655.1,-594.88 h60
  text "REV:" at 3499.6,-594.88 h60
  text ".PCB_Rev" at 3791.1,-594.88 h60
  text "SVN REV:" at 4337.6,-594.88 h60
  text ".VersionControl_RevNumber" at 4843.6,-594.88 h60
  text "LAYER NAME =" at -366.9,-797.71 h60
  text "TID #:" at 2109.6,-798.21 h60
  text ".TID" at 2655.1,-798.21 h60
  text "PLOT NAME =" at -366.9,-1003.55 h60
  text ".plot_File_Name" at 438.6,-1003.55 h60
  text "GENERATED    :" at 2111.6,-1003.55 h60
  text ".Print_Date" at 2981.1,-1003.55 h60
  text ".Print_Time" at 3710.1,-1003.55 h60
  text "TEXAS INSTRUMENTS" at 4974.6,-1003.55 h60
M12 Stackup:
  drawing of 191 lines, arcs and shapes, not listed
  text "Layer" at 9659.44,7890.79 h60
  text "Name" at 10069.36,7890.79 h60
  text "Material" at 10999.1,7890.79 h60
  text "Thickness" at 11858.87,7890.79 h60
  text "Constant" at 12508.7,7890.79 h60
  text "Board Layer Stack" at 13078.56,7890.79 h60
  text "1" at 9659.44,7770.79 h60
  text "Top Overlay" at 10069.36,7770.79 h60
  text "2" at 9659.44,7650.79 h60
  text "Top Solder" at 10069.36,7650.79 h60
  text "Solder Resist" at 10999.1,7650.79 h60
  text "0.40mil" at 11858.87,7650.79 h60
  text "3.5" at 12508.7,7650.79 h60
  text "3" at 9659.44,7530.79 h60
  text "Top Layer" at 10069.36,7530.79 h60
  text "Copper" at 10999.1,7530.79 h60
  text "1.40mil" at 11858.87,7530.79 h60
  text "4" at 9659.44,7410.79 h60
  text "Dielectric1" at 10069.36,7410.79 h60
  text "FR-4" at 10999.1,7410.79 h60
  text "59.20mil" at 11858.87,7410.79 h60
  text "4.8" at 12508.7,7410.79 h60
  text "5" at 9659.44,7290.79 h60
  text "Bottom Layer" at 10069.36,7290.79 h60
  text "Copper" at 10999.1,7290.79 h60
  text "1.40mil" at 11858.87,7290.79 h60
  text "6" at 9659.44,7170.79 h60
  text "Bottom Solder" at 10069.36,7170.79 h60
  text "Solder Resist" at 10999.1,7170.79 h60
  text "0.40mil" at 11858.87,7170.79 h60
  text "3.5" at 12508.7,7170.79 h60
  text "7" at 9659.44,7050.79 h60
  text "Bottom Overlay" at 10069.36,7050.79 h60
  text ".Layer_Name" at 438.6,-797.71 h60
M13 Component Bodies Top:
  text ".Layer_Name" at 438.6,-797.71 h60
M14 Component Bodies Bottom:
  text ".Layer_Name" at 438.6,-797.71 h60
M15 Courtyards Top:
  text ".Layer_Name" at 438.6,-797.71 h60
M16 Courtyards Bottom:
  text ".Layer_Name" at 438.6,-797.71 h60
Drill Drawing:
  text ".Layer_Name" at 438.6,-797.71 h60
M17 Embedded Cavity:
  text ".Layer_Name" at 438.6,-797.71 h60
M18 Embedded Assembly:
  text ".Layer_Name" at 438.6,-797.71 h60
M19 Embedded Keepout:
  text ".Layer_Name" at 438.6,-797.71 h60

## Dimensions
-138.4,-339.21 to 861.6,-339.21 on M2 Board Dimensions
